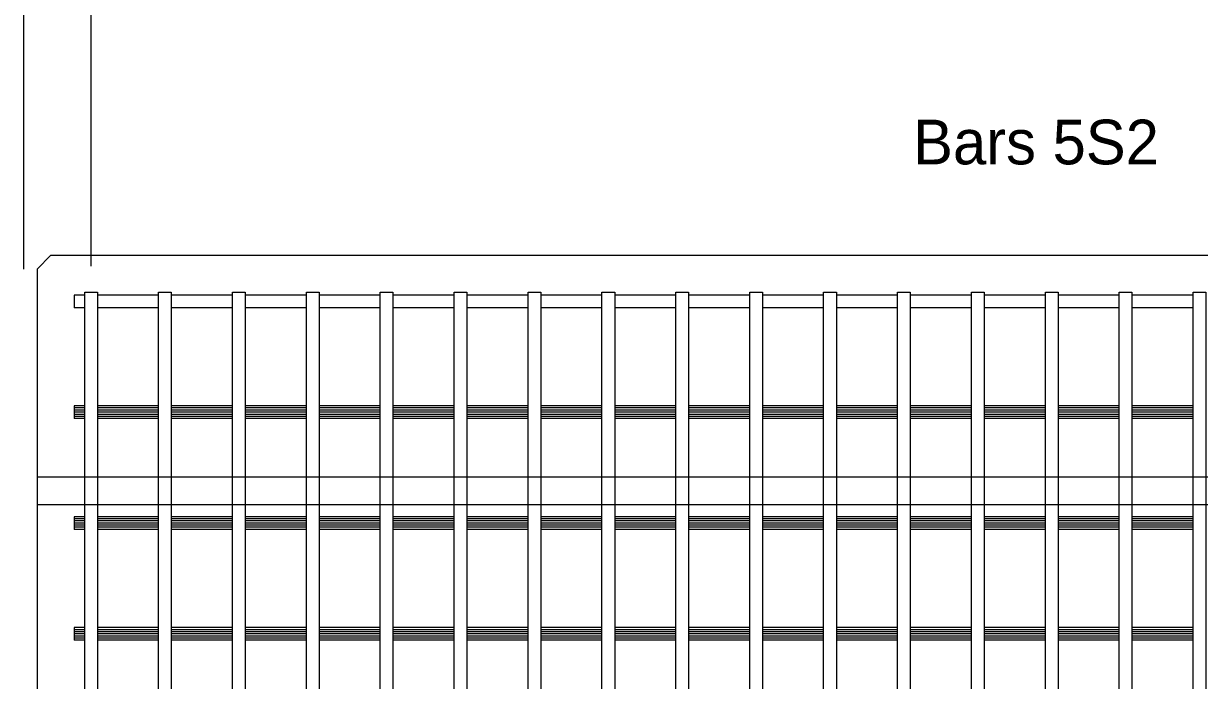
# Model space of a CAD drawing. Extents: x 120587.5 to 120659.6, y 120683.4 to 120715.5.
# Drawn here: x 120598.06 to 120603.37, y 120702.5 to 120705.47 of the extents above; entities that cross this region are included whole.
import ezdxf

# ---------------------------------------------------------------- set-up
doc = ezdxf.new("R2010")
doc.units = 0
for name, color, linetype in [('AdhocPoint_dp', 7, 'Continuous'), ('Border', 7, 'Continuous'), ('PlotBorder_dp', 7, 'Continuous'), ('SheetLines_dp', 7, 'Continuous'), ('TextMisc', 7, 'Continuous')]:
    doc.layers.add(name, color=color, linetype=linetype)

msp = doc.modelspace()

# ---------------------------------------------------------------- linework, layer by layer
at = {"layer": 'AdhocPoint_dp'}
msp.add_line((120598.3674, 120704.3707), (120598.3674, 120706.3004), dxfattribs=at)
at = {"layer": 'Border'}
for p, q in [((120598.2907, 120704.2407), (120598.2907, 120704.1834)), ((120598.3388, 120704.2407), (120598.2907, 120704.2407)), ((120598.6721, 120704.2407), (120598.3961, 120704.2407)), ((120599.0055, 120704.2407), (120598.7294, 120704.2407)), ((120599.3388, 120704.2407), (120599.0628, 120704.2407)), ((120599.6721, 120704.2407), (120599.3961, 120704.2407)), ((120600.0055, 120704.2407), (120599.7294, 120704.2407)), ((120600.3388, 120704.2407), (120600.0628, 120704.2407)), ((120600.6721, 120704.2407), (120600.3961, 120704.2407)), ((120601.0055, 120704.2407), (120600.7294, 120704.2407)), ((120601.3388, 120704.2407), (120601.0628, 120704.2407)), ((120601.6721, 120704.2407), (120601.3961, 120704.2407)), ((120602.0055, 120704.2407), (120601.7294, 120704.2407)), ((120602.3388, 120704.2407), (120602.0628, 120704.2407)), ((120602.6721, 120704.2407), (120602.3961, 120704.2407)), ((120603.0055, 120704.2407), (120602.7294, 120704.2407)), ((120603.3388, 120704.2407), (120603.0628, 120704.2407)), ((120598.3388, 120704.1834), (120598.2907, 120704.1834)), ((120598.6721, 120704.1834), (120598.3961, 120704.1834)), ((120599.0055, 120704.1834), (120598.7294, 120704.1834)), ((120599.3388, 120704.1834), (120599.0628, 120704.1834)), ((120599.6721, 120704.1834), (120599.3961, 120704.1834)), ((120600.0055, 120704.1834), (120599.7294, 120704.1834)), ((120600.3388, 120704.1834), (120600.0628, 120704.1834)), ((120600.6721, 120704.1834), (120600.3961, 120704.1834)), ((120601.0055, 120704.1834), (120600.7294, 120704.1834)), ((120601.3388, 120704.1834), (120601.0628, 120704.1834)), ((120601.6721, 120704.1834), (120601.3961, 120704.1834)), ((120602.0055, 120704.1834), (120601.7294, 120704.1834)), ((120602.3388, 120704.1834), (120602.0628, 120704.1834)), ((120602.6721, 120704.1834), (120602.3961, 120704.1834)), ((120603.0055, 120704.1834), (120602.7294, 120704.1834)), ((120603.3388, 120704.1834), (120603.0628, 120704.1834)), ((120598.2907, 120703.7407), (120598.2907, 120703.6834)), ((120598.3388, 120703.7407), (120598.2907, 120703.7407)), ((120598.3388, 120703.7311), (120598.2907, 120703.7311)), ((120598.3388, 120703.7216), (120598.2907, 120703.7216)), ((120598.3388, 120703.712), (120598.2907, 120703.712)), ((120598.6721, 120703.7407), (120598.3961, 120703.7407)), ((120598.6721, 120703.7311), (120598.3961, 120703.7311)), ((120598.6721, 120703.7216), (120598.3961, 120703.7216)), ((120598.6721, 120703.712), (120598.3961, 120703.712)), ((120599.0055, 120703.7407), (120598.7294, 120703.7407)), ((120599.0055, 120703.7311), (120598.7294, 120703.7311)), ((120599.0055, 120703.7216), (120598.7294, 120703.7216)), ((120599.0055, 120703.712), (120598.7294, 120703.712)), ((120599.3388, 120703.7407), (120599.0628, 120703.7407)), ((120599.3388, 120703.7311), (120599.0628, 120703.7311)), ((120599.3388, 120703.7216), (120599.0628, 120703.7216)), ((120599.3388, 120703.712), (120599.0628, 120703.712)), ((120599.6721, 120703.7407), (120599.3961, 120703.7407)), ((120599.6721, 120703.7311), (120599.3961, 120703.7311)), ((120599.6721, 120703.7216), (120599.3961, 120703.7216)), ((120599.6721, 120703.712), (120599.3961, 120703.712)), ((120600.0055, 120703.7407), (120599.7294, 120703.7407)), ((120600.0055, 120703.7311), (120599.7294, 120703.7311)), ((120600.0055, 120703.7216), (120599.7294, 120703.7216)), ((120600.0055, 120703.712), (120599.7294, 120703.712)), ((120600.3388, 120703.7407), (120600.0628, 120703.7407)), ((120600.3388, 120703.7311), (120600.0628, 120703.7311)), ((120600.3388, 120703.7216), (120600.0628, 120703.7216)), ((120600.3388, 120703.712), (120600.0628, 120703.712)), ((120600.6721, 120703.7407), (120600.3961, 120703.7407)), ((120600.6721, 120703.7311), (120600.3961, 120703.7311)), ((120600.6721, 120703.7216), (120600.3961, 120703.7216)), ((120600.6721, 120703.712), (120600.3961, 120703.712)), ((120601.0055, 120703.7407), (120600.7294, 120703.7407)), ((120601.0055, 120703.7311), (120600.7294, 120703.7311)), ((120601.0055, 120703.7216), (120600.7294, 120703.7216)), ((120601.0055, 120703.712), (120600.7294, 120703.712)), ((120601.3388, 120703.7407), (120601.0628, 120703.7407)), ((120601.3388, 120703.7311), (120601.0628, 120703.7311)), ((120601.3388, 120703.7216), (120601.0628, 120703.7216)), ((120601.3388, 120703.712), (120601.0628, 120703.712)), ((120601.6721, 120703.7407), (120601.3961, 120703.7407)), ((120601.6721, 120703.7311), (120601.3961, 120703.7311)), ((120601.6721, 120703.7216), (120601.3961, 120703.7216)), ((120601.6721, 120703.712), (120601.3961, 120703.712)), ((120602.0055, 120703.7407), (120601.7294, 120703.7407)), ((120602.0055, 120703.7311), (120601.7294, 120703.7311)), ((120602.0055, 120703.7216), (120601.7294, 120703.7216)), ((120602.0055, 120703.712), (120601.7294, 120703.712)), ((120602.3388, 120703.7407), (120602.0628, 120703.7407)), ((120602.3388, 120703.7311), (120602.0628, 120703.7311)), ((120602.3388, 120703.7216), (120602.0628, 120703.7216)), ((120602.3388, 120703.712), (120602.0628, 120703.712)), ((120602.6721, 120703.7407), (120602.3961, 120703.7407)), ((120602.6721, 120703.7311), (120602.3961, 120703.7311)), ((120602.6721, 120703.7216), (120602.3961, 120703.7216)), ((120602.6721, 120703.712), (120602.3961, 120703.712)), ((120603.0055, 120703.7407), (120602.7294, 120703.7407)), ((120603.0055, 120703.7311), (120602.7294, 120703.7311)), ((120603.0055, 120703.7216), (120602.7294, 120703.7216)), ((120603.0055, 120703.712), (120602.7294, 120703.712)), ((120603.3388, 120703.7407), (120603.0628, 120703.7407)), ((120603.3388, 120703.7311), (120603.0628, 120703.7311)), ((120603.3388, 120703.7216), (120603.0628, 120703.7216)), ((120603.3388, 120703.712), (120603.0628, 120703.712)), ((120598.3388, 120703.7025), (120598.2907, 120703.7025)), ((120598.3388, 120703.6929), (120598.2907, 120703.6929)), ((120598.3388, 120703.6834), (120598.2907, 120703.6834)), ((120598.6721, 120703.7025), (120598.3961, 120703.7025)), ((120598.6721, 120703.6929), (120598.3961, 120703.6929)), ((120598.6721, 120703.6834), (120598.3961, 120703.6834)), ((120599.0055, 120703.7025), (120598.7294, 120703.7025)), ((120599.0055, 120703.6929), (120598.7294, 120703.6929)), ((120599.0055, 120703.6834), (120598.7294, 120703.6834)), ((120599.3388, 120703.7025), (120599.0628, 120703.7025)), ((120599.3388, 120703.6929), (120599.0628, 120703.6929)), ((120599.3388, 120703.6834), (120599.0628, 120703.6834)), ((120599.6721, 120703.7025), (120599.3961, 120703.7025)), ((120599.6721, 120703.6929), (120599.3961, 120703.6929)), ((120599.6721, 120703.6834), (120599.3961, 120703.6834)), ((120600.0055, 120703.7025), (120599.7294, 120703.7025)), ((120600.0055, 120703.6929), (120599.7294, 120703.6929)), ((120600.0055, 120703.6834), (120599.7294, 120703.6834)), ((120600.3388, 120703.7025), (120600.0628, 120703.7025)), ((120600.3388, 120703.6929), (120600.0628, 120703.6929)), ((120600.3388, 120703.6834), (120600.0628, 120703.6834)), ((120600.6721, 120703.7025), (120600.3961, 120703.7025)), ((120600.6721, 120703.6929), (120600.3961, 120703.6929)), ((120600.6721, 120703.6834), (120600.3961, 120703.6834)), ((120601.0055, 120703.7025), (120600.7294, 120703.7025)), ((120601.0055, 120703.6929), (120600.7294, 120703.6929)), ((120601.0055, 120703.6834), (120600.7294, 120703.6834)), ((120601.3388, 120703.7025), (120601.0628, 120703.7025)), ((120601.3388, 120703.6929), (120601.0628, 120703.6929)), ((120601.3388, 120703.6834), (120601.0628, 120703.6834)), ((120601.6721, 120703.7025), (120601.3961, 120703.7025)), ((120601.6721, 120703.6929), (120601.3961, 120703.6929)), ((120601.6721, 120703.6834), (120601.3961, 120703.6834)), ((120602.0055, 120703.7025), (120601.7294, 120703.7025)), ((120602.0055, 120703.6929), (120601.7294, 120703.6929)), ((120602.0055, 120703.6834), (120601.7294, 120703.6834)), ((120602.3388, 120703.7025), (120602.0628, 120703.7025)), ((120602.3388, 120703.6929), (120602.0628, 120703.6929)), ((120602.3388, 120703.6834), (120602.0628, 120703.6834)), ((120602.6721, 120703.7025), (120602.3961, 120703.7025)), ((120602.6721, 120703.6929), (120602.3961, 120703.6929)), ((120602.6721, 120703.6834), (120602.3961, 120703.6834)), ((120603.0055, 120703.7025), (120602.7294, 120703.7025)), ((120603.0055, 120703.6929), (120602.7294, 120703.6929)), ((120603.0055, 120703.6834), (120602.7294, 120703.6834)), ((120603.3388, 120703.7025), (120603.0628, 120703.7025)), ((120603.3388, 120703.6929), (120603.0628, 120703.6929)), ((120603.3388, 120703.6834), (120603.0628, 120703.6834)), ((120598.2907, 120703.2407), (120598.2907, 120703.1834)), ((120598.3388, 120703.2407), (120598.2907, 120703.2407)), ((120598.6721, 120703.2407), (120598.3961, 120703.2407)), ((120599.0055, 120703.2407), (120598.7294, 120703.2407)), ((120599.3388, 120703.2407), (120599.0628, 120703.2407)), ((120599.6721, 120703.2407), (120599.3961, 120703.2407)), ((120600.0055, 120703.2407), (120599.7294, 120703.2407)), ((120600.3388, 120703.2407), (120600.0628, 120703.2407)), ((120600.6721, 120703.2407), (120600.3961, 120703.2407)), ((120601.0055, 120703.2407), (120600.7294, 120703.2407)), ((120601.3388, 120703.2407), (120601.0628, 120703.2407)), ((120601.6721, 120703.2407), (120601.3961, 120703.2407)), ((120602.0055, 120703.2407), (120601.7294, 120703.2407)), ((120602.3388, 120703.2407), (120602.0628, 120703.2407)), ((120602.6721, 120703.2407), (120602.3961, 120703.2407)), ((120603.0055, 120703.2407), (120602.7294, 120703.2407)), ((120603.3388, 120703.2407), (120603.0628, 120703.2407)), ((120598.3388, 120703.2311), (120598.2907, 120703.2311)), ((120598.3388, 120703.2216), (120598.2907, 120703.2216)), ((120598.3388, 120703.212), (120598.2907, 120703.212)), ((120598.3388, 120703.2025), (120598.2907, 120703.2025)), ((120598.3388, 120703.1929), (120598.2907, 120703.1929)), ((120598.3388, 120703.1834), (120598.2907, 120703.1834)), ((120598.6721, 120703.2311), (120598.3961, 120703.2311)), ((120598.6721, 120703.2216), (120598.3961, 120703.2216)), ((120598.6721, 120703.212), (120598.3961, 120703.212)), ((120598.6721, 120703.2025), (120598.3961, 120703.2025)), ((120598.6721, 120703.1929), (120598.3961, 120703.1929)), ((120598.6721, 120703.1834), (120598.3961, 120703.1834)), ((120599.0055, 120703.2311), (120598.7294, 120703.2311)), ((120599.0055, 120703.2216), (120598.7294, 120703.2216)), ((120599.0055, 120703.212), (120598.7294, 120703.212)), ((120599.0055, 120703.2025), (120598.7294, 120703.2025)), ((120599.0055, 120703.1929), (120598.7294, 120703.1929)), ((120599.0055, 120703.1834), (120598.7294, 120703.1834)), ((120599.3388, 120703.2311), (120599.0628, 120703.2311)), ((120599.3388, 120703.2216), (120599.0628, 120703.2216)), ((120599.3388, 120703.212), (120599.0628, 120703.212)), ((120599.3388, 120703.2025), (120599.0628, 120703.2025)), ((120599.3388, 120703.1929), (120599.0628, 120703.1929)), ((120599.3388, 120703.1834), (120599.0628, 120703.1834)), ((120599.6721, 120703.2311), (120599.3961, 120703.2311)), ((120599.6721, 120703.2216), (120599.3961, 120703.2216)), ((120599.6721, 120703.212), (120599.3961, 120703.212)), ((120599.6721, 120703.2025), (120599.3961, 120703.2025)), ((120599.6721, 120703.1929), (120599.3961, 120703.1929)), ((120599.6721, 120703.1834), (120599.3961, 120703.1834)), ((120600.0055, 120703.2311), (120599.7294, 120703.2311)), ((120600.0055, 120703.2216), (120599.7294, 120703.2216)), ((120600.0055, 120703.212), (120599.7294, 120703.212)), ((120600.0055, 120703.2025), (120599.7294, 120703.2025)), ((120600.0055, 120703.1929), (120599.7294, 120703.1929)), ((120600.0055, 120703.1834), (120599.7294, 120703.1834)), ((120600.3388, 120703.2311), (120600.0628, 120703.2311)), ((120600.3388, 120703.2216), (120600.0628, 120703.2216)), ((120600.3388, 120703.212), (120600.0628, 120703.212)), ((120600.3388, 120703.2025), (120600.0628, 120703.2025)), ((120600.3388, 120703.1929), (120600.0628, 120703.1929)), ((120600.3388, 120703.1834), (120600.0628, 120703.1834)), ((120600.6721, 120703.2311), (120600.3961, 120703.2311)), ((120600.6721, 120703.2216), (120600.3961, 120703.2216)), ((120600.6721, 120703.212), (120600.3961, 120703.212)), ((120600.6721, 120703.2025), (120600.3961, 120703.2025)), ((120600.6721, 120703.1929), (120600.3961, 120703.1929)), ((120600.6721, 120703.1834), (120600.3961, 120703.1834)), ((120601.0055, 120703.2311), (120600.7294, 120703.2311)), ((120601.0055, 120703.2216), (120600.7294, 120703.2216)), ((120601.0055, 120703.212), (120600.7294, 120703.212)), ((120601.0055, 120703.2025), (120600.7294, 120703.2025)), ((120601.0055, 120703.1929), (120600.7294, 120703.1929)), ((120601.0055, 120703.1834), (120600.7294, 120703.1834)), ((120601.3388, 120703.2311), (120601.0628, 120703.2311)), ((120601.3388, 120703.2216), (120601.0628, 120703.2216)), ((120601.3388, 120703.212), (120601.0628, 120703.212)), ((120601.3388, 120703.2025), (120601.0628, 120703.2025)), ((120601.3388, 120703.1929), (120601.0628, 120703.1929)), ((120601.3388, 120703.1834), (120601.0628, 120703.1834)), ((120601.6721, 120703.2311), (120601.3961, 120703.2311)), ((120601.6721, 120703.2216), (120601.3961, 120703.2216)), ((120601.6721, 120703.212), (120601.3961, 120703.212)), ((120601.6721, 120703.2025), (120601.3961, 120703.2025)), ((120601.6721, 120703.1929), (120601.3961, 120703.1929)), ((120601.6721, 120703.1834), (120601.3961, 120703.1834)), ((120602.0055, 120703.2311), (120601.7294, 120703.2311)), ((120602.0055, 120703.2216), (120601.7294, 120703.2216)), ((120602.0055, 120703.212), (120601.7294, 120703.212)), ((120602.0055, 120703.2025), (120601.7294, 120703.2025)), ((120602.0055, 120703.1929), (120601.7294, 120703.1929)), ((120602.0055, 120703.1834), (120601.7294, 120703.1834)), ((120602.3388, 120703.2311), (120602.0628, 120703.2311)), ((120602.3388, 120703.2216), (120602.0628, 120703.2216)), ((120602.3388, 120703.212), (120602.0628, 120703.212)), ((120602.3388, 120703.2025), (120602.0628, 120703.2025)), ((120602.3388, 120703.1929), (120602.0628, 120703.1929)), ((120602.3388, 120703.1834), (120602.0628, 120703.1834)), ((120602.6721, 120703.2311), (120602.3961, 120703.2311)), ((120602.6721, 120703.2216), (120602.3961, 120703.2216)), ((120602.6721, 120703.212), (120602.3961, 120703.212)), ((120602.6721, 120703.2025), (120602.3961, 120703.2025)), ((120602.6721, 120703.1929), (120602.3961, 120703.1929)), ((120602.6721, 120703.1834), (120602.3961, 120703.1834)), ((120603.0055, 120703.2311), (120602.7294, 120703.2311)), ((120603.0055, 120703.2216), (120602.7294, 120703.2216)), ((120603.0055, 120703.212), (120602.7294, 120703.212)), ((120603.0055, 120703.2025), (120602.7294, 120703.2025)), ((120603.0055, 120703.1929), (120602.7294, 120703.1929)), ((120603.0055, 120703.1834), (120602.7294, 120703.1834)), ((120603.3388, 120703.2311), (120603.0628, 120703.2311)), ((120603.3388, 120703.2216), (120603.0628, 120703.2216)), ((120603.3388, 120703.212), (120603.0628, 120703.212)), ((120603.3388, 120703.2025), (120603.0628, 120703.2025)), ((120603.3388, 120703.1929), (120603.0628, 120703.1929)), ((120603.3388, 120703.1834), (120603.0628, 120703.1834)), ((120598.2907, 120702.7407), (120598.2907, 120702.6834)), ((120598.3388, 120702.7407), (120598.2907, 120702.7407)), ((120598.3388, 120702.7311), (120598.2907, 120702.7311)), ((120598.3388, 120702.7216), (120598.2907, 120702.7216)), ((120598.3388, 120702.712), (120598.2907, 120702.712)), ((120598.3388, 120702.7025), (120598.2907, 120702.7025)), ((120598.6721, 120702.7407), (120598.3961, 120702.7407)), ((120598.6721, 120702.7311), (120598.3961, 120702.7311)), ((120598.6721, 120702.7216), (120598.3961, 120702.7216)), ((120598.6721, 120702.712), (120598.3961, 120702.712)), ((120598.6721, 120702.7025), (120598.3961, 120702.7025)), ((120599.0055, 120702.7407), (120598.7294, 120702.7407)), ((120599.0055, 120702.7311), (120598.7294, 120702.7311)), ((120599.0055, 120702.7216), (120598.7294, 120702.7216)), ((120599.0055, 120702.712), (120598.7294, 120702.712)), ((120599.0055, 120702.7025), (120598.7294, 120702.7025)), ((120599.3388, 120702.7407), (120599.0628, 120702.7407)), ((120599.3388, 120702.7311), (120599.0628, 120702.7311)), ((120599.3388, 120702.7216), (120599.0628, 120702.7216)), ((120599.3388, 120702.712), (120599.0628, 120702.712)), ((120599.3388, 120702.7025), (120599.0628, 120702.7025)), ((120599.6721, 120702.7407), (120599.3961, 120702.7407)), ((120599.6721, 120702.7311), (120599.3961, 120702.7311)), ((120599.6721, 120702.7216), (120599.3961, 120702.7216)), ((120599.6721, 120702.712), (120599.3961, 120702.712)), ((120599.6721, 120702.7025), (120599.3961, 120702.7025)), ((120600.0055, 120702.7407), (120599.7294, 120702.7407)), ((120600.0055, 120702.7311), (120599.7294, 120702.7311)), ((120600.0055, 120702.7216), (120599.7294, 120702.7216)), ((120600.0055, 120702.712), (120599.7294, 120702.712)), ((120600.0055, 120702.7025), (120599.7294, 120702.7025)), ((120600.3388, 120702.7407), (120600.0628, 120702.7407)), ((120600.3388, 120702.7311), (120600.0628, 120702.7311)), ((120600.3388, 120702.7216), (120600.0628, 120702.7216)), ((120600.3388, 120702.712), (120600.0628, 120702.712)), ((120600.3388, 120702.7025), (120600.0628, 120702.7025)), ((120600.6721, 120702.7407), (120600.3961, 120702.7407)), ((120600.6721, 120702.7311), (120600.3961, 120702.7311)), ((120600.6721, 120702.7216), (120600.3961, 120702.7216)), ((120600.6721, 120702.712), (120600.3961, 120702.712)), ((120600.6721, 120702.7025), (120600.3961, 120702.7025)), ((120601.0055, 120702.7407), (120600.7294, 120702.7407)), ((120601.0055, 120702.7311), (120600.7294, 120702.7311)), ((120601.0055, 120702.7216), (120600.7294, 120702.7216)), ((120601.0055, 120702.712), (120600.7294, 120702.712)), ((120601.0055, 120702.7025), (120600.7294, 120702.7025)), ((120601.3388, 120702.7407), (120601.0628, 120702.7407)), ((120601.3388, 120702.7311), (120601.0628, 120702.7311)), ((120601.3388, 120702.7216), (120601.0628, 120702.7216)), ((120601.3388, 120702.712), (120601.0628, 120702.712)), ((120601.3388, 120702.7025), (120601.0628, 120702.7025)), ((120601.6721, 120702.7407), (120601.3961, 120702.7407)), ((120601.6721, 120702.7311), (120601.3961, 120702.7311)), ((120601.6721, 120702.7216), (120601.3961, 120702.7216)), ((120601.6721, 120702.712), (120601.3961, 120702.712)), ((120601.6721, 120702.7025), (120601.3961, 120702.7025)), ((120602.0055, 120702.7407), (120601.7294, 120702.7407)), ((120602.0055, 120702.7311), (120601.7294, 120702.7311)), ((120602.0055, 120702.7216), (120601.7294, 120702.7216)), ((120602.0055, 120702.712), (120601.7294, 120702.712)), ((120602.0055, 120702.7025), (120601.7294, 120702.7025)), ((120602.3388, 120702.7407), (120602.0628, 120702.7407)), ((120602.3388, 120702.7311), (120602.0628, 120702.7311)), ((120602.3388, 120702.7216), (120602.0628, 120702.7216)), ((120602.3388, 120702.712), (120602.0628, 120702.712)), ((120602.3388, 120702.7025), (120602.0628, 120702.7025)), ((120602.6721, 120702.7407), (120602.3961, 120702.7407)), ((120602.6721, 120702.7311), (120602.3961, 120702.7311)), ((120602.6721, 120702.7216), (120602.3961, 120702.7216)), ((120602.6721, 120702.712), (120602.3961, 120702.712)), ((120602.6721, 120702.7025), (120602.3961, 120702.7025)), ((120603.0055, 120702.7407), (120602.7294, 120702.7407)), ((120603.0055, 120702.7311), (120602.7294, 120702.7311)), ((120603.0055, 120702.7216), (120602.7294, 120702.7216)), ((120603.0055, 120702.712), (120602.7294, 120702.712)), ((120603.0055, 120702.7025), (120602.7294, 120702.7025)), ((120603.3388, 120702.7407), (120603.0628, 120702.7407)), ((120603.3388, 120702.7311), (120603.0628, 120702.7311)), ((120603.3388, 120702.7216), (120603.0628, 120702.7216)), ((120603.3388, 120702.712), (120603.0628, 120702.712)), ((120603.3388, 120702.7025), (120603.0628, 120702.7025)), ((120598.3388, 120702.6929), (120598.2907, 120702.6929)), ((120598.3388, 120702.6834), (120598.2907, 120702.6834)), ((120598.6721, 120702.6929), (120598.3961, 120702.6929)), ((120598.6721, 120702.6834), (120598.3961, 120702.6834)), ((120599.0055, 120702.6929), (120598.7294, 120702.6929)), ((120599.0055, 120702.6834), (120598.7294, 120702.6834)), ((120599.3388, 120702.6929), (120599.0628, 120702.6929)), ((120599.3388, 120702.6834), (120599.0628, 120702.6834)), ((120599.6721, 120702.6929), (120599.3961, 120702.6929)), ((120599.6721, 120702.6834), (120599.3961, 120702.6834)), ((120600.0055, 120702.6929), (120599.7294, 120702.6929)), ((120600.0055, 120702.6834), (120599.7294, 120702.6834)), ((120600.3388, 120702.6929), (120600.0628, 120702.6929)), ((120600.3388, 120702.6834), (120600.0628, 120702.6834)), ((120600.6721, 120702.6929), (120600.3961, 120702.6929)), ((120600.6721, 120702.6834), (120600.3961, 120702.6834)), ((120601.0055, 120702.6929), (120600.7294, 120702.6929)), ((120601.0055, 120702.6834), (120600.7294, 120702.6834)), ((120601.3388, 120702.6929), (120601.0628, 120702.6929)), ((120601.3388, 120702.6834), (120601.0628, 120702.6834)), ((120601.6721, 120702.6929), (120601.3961, 120702.6929)), ((120601.6721, 120702.6834), (120601.3961, 120702.6834)), ((120602.0055, 120702.6929), (120601.7294, 120702.6929)), ((120602.0055, 120702.6834), (120601.7294, 120702.6834)), ((120602.3388, 120702.6929), (120602.0628, 120702.6929)), ((120602.3388, 120702.6834), (120602.0628, 120702.6834)), ((120602.6721, 120702.6929), (120602.3961, 120702.6929)), ((120602.6721, 120702.6834), (120602.3961, 120702.6834)), ((120603.0055, 120702.6929), (120602.7294, 120702.6929)), ((120603.0055, 120702.6834), (120602.7294, 120702.6834)), ((120603.3388, 120702.6929), (120603.0628, 120702.6929)), ((120603.3388, 120702.6834), (120603.0628, 120702.6834))]:
    msp.add_line(p, q, dxfattribs=at)
for points in [[(120598.3388, 120704.2537), (120598.3961, 120704.2537), (120598.3961, 120696.4204), (120598.3388, 120696.4204)], [(120598.6721, 120704.2537), (120598.7294, 120704.2537), (120598.7294, 120696.4204), (120598.6721, 120696.4204)], [(120599.0055, 120704.2537), (120599.0628, 120704.2537), (120599.0628, 120696.4204), (120599.0055, 120696.4204)], [(120599.3388, 120704.2537), (120599.3961, 120704.2537), (120599.3961, 120696.4203), (120599.3388, 120696.4203)], [(120599.6721, 120704.2537), (120599.7294, 120704.2537), (120599.7294, 120696.4203), (120599.6721, 120696.4203)], [(120600.0055, 120704.2537), (120600.0628, 120704.2537), (120600.0628, 120696.4203), (120600.0055, 120696.4203)], [(120600.3388, 120704.2537), (120600.3961, 120704.2537), (120600.3961, 120696.4203), (120600.3388, 120696.4203)], [(120600.6721, 120704.2537), (120600.7294, 120704.2537), (120600.7294, 120696.4203), (120600.6721, 120696.4203)], [(120601.0055, 120704.2537), (120601.0628, 120704.2537), (120601.0628, 120696.4203), (120601.0055, 120696.4203)], [(120601.3388, 120704.2537), (120601.3961, 120704.2537), (120601.3961, 120696.4203), (120601.3388, 120696.4203)], [(120601.6721, 120704.2537), (120601.7294, 120704.2537), (120601.7294, 120696.4203), (120601.6721, 120696.4203)], [(120602.0055, 120704.2537), (120602.0628, 120704.2537), (120602.0628, 120696.4203), (120602.0055, 120696.4203)], [(120602.3388, 120704.2537), (120602.3961, 120704.2537), (120602.3961, 120696.4203), (120602.3388, 120696.4203)], [(120602.6721, 120704.2537), (120602.7294, 120704.2537), (120602.7294, 120696.4203), (120602.6721, 120696.4203)], [(120603.0055, 120704.2537), (120603.0628, 120704.2537), (120603.0628, 120696.4203), (120603.0055, 120696.4203)], [(120603.3388, 120704.2537), (120603.3961, 120704.2537), (120603.3961, 120696.4203), (120603.3388, 120696.4203)]]:
    msp.add_lwpolyline(points, close=True, dxfattribs=at)
at = {"layer": 'PlotBorder_dp'}
for p, q in [((120598.1865, 120704.4203), (120598.124, 120704.3578)), ((120598.1865, 120704.4203), (120607.6672, 120704.4203)), ((120598.124, 120704.3578), (120598.124, 120696.4204)), ((120598.124, 120703.4203), (120603.7822, 120703.4203)), ((120598.124, 120703.2953), (120603.7822, 120703.2953))]:
    msp.add_line(p, q, dxfattribs=at)
at = {"layer": 'SheetLines_dp'}
msp.add_line((120598.0628, 120707.5627), (120598.0628, 120704.3578), dxfattribs=at)

# ---------------------------------------------------------------- texts
at = {"layer": 'TextMisc'}
msp.add_text('Bars 5S2', height=0.2016, dxfattribs=at).set_placement((120602.0755, 120704.83))

doc.saveas('drawing.dxf')
